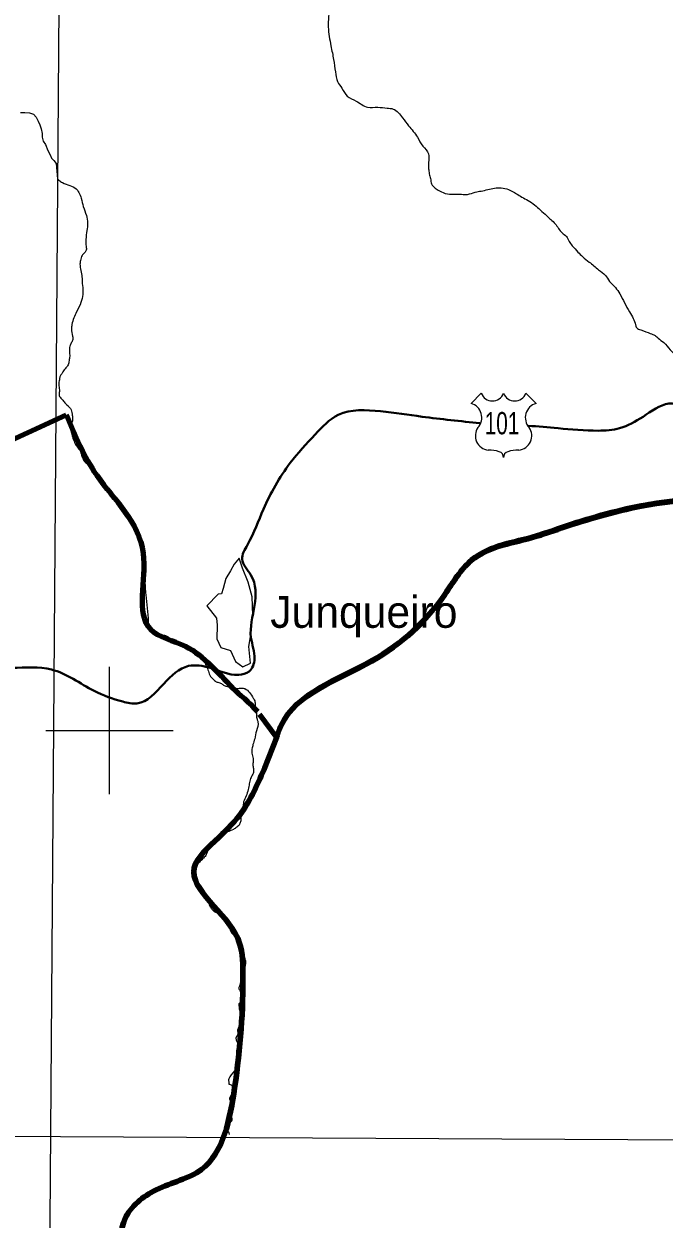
# Model space of a CAD drawing. Extents: x -1643653 to 4543381, y 1624270 to 13878484.
# Drawn here: x 773658 to 783704, y 8892328 to 8911096 of the extents above; entities that cross this region are included whole.
import ezdxf
from ezdxf.enums import TextEntityAlignment as Align

# ---------------------------------------------------------------- set-up
doc = ezdxf.new("R2010")
doc.units = 0
doc.header["$LTSCALE"] = 200
for name, color, linetype, lineweight in [('1', 7, 'Continuous', 13), ('12', 7, 'Continuous', 25), ('2', 7, 'Continuous', 13), ('21', 7, 'Continuous', 25), ('24', 7, 'Continuous', 25), ('48', 7, 'Continuous', 25), ('60', 7, 'Continuous', 13), ('9', 7, 'Continuous', 90)]:
    doc.layers.add(name, color=color, linetype=linetype, lineweight=lineweight)
doc.layers.add('41', color=7, linetype='Continuous')

msp = doc.modelspace()

# ---------------------------------------------------------------- linework, layer by layer
at = {"layer": '1'}
for points in [[(774987.1, 9020818), (774482.3, 8948876), (774053.6, 8890875.3)], [(564751.7, 8894587.5), (664411.9, 8894209.9), (791388.5, 8893536.2)]]:
    msp.add_lwpolyline(points, dxfattribs=at)
at = {"layer": '12', "lineweight": 40}
for points in [[(781569.2, 8904786.7), (782039.7, 8904747.1), (782669.3, 8904708.5), (783006.7, 8904747.1), (783373.7, 8904928.3), (783777.7, 8905132.8), (784291.7, 8905049.2), (784468.4, 8905065.3), (784754.3, 8905737.1), (785107.7, 8905939.5), (785694.7, 8905935.1), (786283.6, 8906023.1), (786505.7, 8906018.9), (787086.7, 8905742.8), (787462.6, 8905479.4)], [(762623.9, 8893658.6), (765112.7, 8894889), (765616.1, 8895112.7), (766035.6, 8895168.6), (766622.8, 8895168.6), (767098.2, 8895308.5), (767433.8, 8895644), (767797.3, 8896343.2), (767965.1, 8896650.8), (768216.8, 8896818.6), (768636.3, 8897489.7), (769335.4, 8898552.4), (769698.9, 8899027.8), (770118.4, 8899810.8), (770454, 8900314.2), (770957.3, 8900677.7), (771712.4, 8900845.5), (772663.2, 8901013.3), (773474.2, 8900985.3), (774089.4, 8900957.3), (774760.5, 8900621.8), (775208, 8900454), (775431.7, 8900426), (775851.2, 8900733.6), (776242.7, 8901013.3), (776578.2, 8900985.3), (777025.7, 8900873.4), (777193.5, 8900929.4), (777277.3, 8901125.1), (777221.4, 8901460.7), (777277.3, 8901964.1), (777221.4, 8902439.5), (777081.6, 8902691.1), (777165.5, 8902914.9), (777417.2, 8903474.2), (777836.6, 8904201.2), (778228.2, 8904648.7), (778591.7, 8904956.3), (779254.3, 8905013.8), (779906, 8904928.3), (780814.8, 8904826.8)]]:
    msp.add_spline(points, degree=3, dxfattribs=at)
at = {"layer": '2'}
for p, q in [((775000, 8899000), (775000, 8901000)), ((774000, 8900000), (776000, 8900000))]:
    msp.add_line(p, q, dxfattribs=at)
at = {"layer": '21'}
msp.add_lwpolyline([(777212.9, 8901059.9), (777186.4, 8901318), (777216.7, 8901500.2), (777250.9, 8901811.5), (777239.5, 8902100), (777175, 8902327.7), (777087.7, 8902547.9), (777034.5, 8902707.3), (776958.6, 8902612.4), (776897.9, 8902509.9), (776825.7, 8902388.4), (776784, 8902232.8), (776761.2, 8902145.5), (776708.1, 8902141.7), (776525.9, 8901955.7), (776681.5, 8901765.9), (776692.9, 8901652), (776685.3, 8901439.5), (776746, 8901302.8), (776897.9, 8901257.2), (776977.6, 8901082.6), (777095.2, 8900999.1)], close=True, dxfattribs=at)
at = {"layer": '24'}
msp.add_lwpolyline([(773604.5, 8909706.9), (773670.6, 8909706.5), (773746.8, 8909700.9), (773807.7, 8909680.2), (773848.1, 8909634), (773883.2, 8909567.6), (773908.3, 8909511.4), (773928.2, 8909450.2), (773942.9, 8909373.7), (773942.6, 8909317.6), (773957.4, 8909256.4), (773997.7, 8909200.1), (774032.7, 8909108.2), (774072.8, 8909031.5), (774092.9, 8908985.6), (774128.2, 8908949.7), (774163.5, 8908903.6), (774185.6, 8908665.7)], dxfattribs=at)
for points in [[(777617.6, 8912828.3), (777839.2, 8912869.9), (777991.6, 8912793.7), (778178.6, 8912766), (778455.7, 8912835.2), (778621.9, 8912856), (778760.5, 8912849.1), (778843.6, 8912745.2), (778864.3, 8912662.1), (778912.8, 8912502.8), (778850.5, 8912322.7), (778739.7, 8912191.1), (778663.5, 8912045.6), (778573.4, 8911865.5), (778497.2, 8911657.7), (778455.7, 8911366.8), (778434.9, 8911048.2), (778476.5, 8910750.4), (778518, 8910535.6), (778545.7, 8910341.7), (778580.4, 8910189.3), (778649.6, 8910085.4), (778732.8, 8909960.8), (778871.3, 8909884.6), (779051.4, 8909787.6), (779210.7, 8909787.6), (779356.1, 8909773.7), (779453.1, 8909759.9), (779598.6, 8909621.3), (779695.5, 8909496.7), (779834.1, 8909316.6), (779917.2, 8909178.1), (780007.2, 8909053.4), (780007.2, 8908921.8), (780009.3, 8908822.2), (780018.8, 8908742.2), (780037.6, 8908666.9), (780056.4, 8908582.2), (780110.5, 8908518.7), (780178.7, 8908476.4), (780303.4, 8908427), (780439.8, 8908424.6), (780552.7, 8908419.9), (780618.6, 8908419.9), (780740.9, 8908452.8), (780832.7, 8908471.7), (780938.5, 8908495.2), (781042, 8908518.7), (781150.2, 8908521.1), (781263.2, 8908495.2), (781387.8, 8908429.3), (781472.5, 8908377.6), (781569, 8908323.5), (781672.5, 8908252.9), (781759.5, 8908175.3)], [(774185.6, 8908665.7), (774206.6, 8908640.3), (774262.2, 8908604.4), (774377, 8908558), (774477.9, 8908507), (774520.8, 8908450.2), (774556.7, 8908357.5), (774590.3, 8908228.8), (774637.8, 8908089.7), (774657, 8907966.8), (774646.5, 8907852.1), (774629.1, 8907712.9), (774632.6, 8907601.7), (774636.1, 8907542.5), (774608.3, 8907500.8), (774570, 8907459.1), (774545.7, 8907382.6), (774537.9, 8907322.4), (774546.2, 8907252.2), (774566.8, 8907147.9), (774572, 8907048.8), (774582.3, 8906929.1), (774580.2, 8906846.2), (774553.4, 8906721.3), (774483.2, 8906572.6), (774441.9, 8906478.6), (774411, 8906374.3), (774403.7, 8906304.8), (774420.2, 8906190.2), (774426.4, 8906138.5), (774400.6, 8906085.9), (774376.9, 8906034.2), (774372.8, 8905948.5), (774375.9, 8905877.3), (774365.5, 8905808.1), (774350, 8905739.9), (774314.9, 8905694.5), (774270.6, 8905633.5), (774243.7, 8905593.3), (774221, 8905553), (774216.9, 8905506.5), (774205.5, 8905472.4), (774207.6, 8905414.6), (774213.8, 8905325.8), (774211.7, 8905257.6), (774247.8, 8905209.1), (774287.1, 8905162.6), (774350, 8905098.6), (774387.2, 8905056.3), (774415, 8904970.4), (774420.2, 8904906.4), (774418.1, 8904863), (774400.6, 8904807.3), (774394.4, 8904756.7), (774392.3, 8904706.1)], [(781759.5, 8908175.3), (781863, 8908083.5), (781926.5, 8908022.4), (781997.1, 8907957.2), (782102.9, 8907815.9), (782171.2, 8907759.5), (782213.5, 8907679.4), (782262.9, 8907613.6), (782352.3, 8907512.3), (782425.2, 8907441.7), (782531.1, 8907357), (782676.9, 8907234.6), (782782.8, 8907147.6), (782848.6, 8907053.4), (782940.4, 8906956.9), (783011, 8906855.7), (783159.2, 8906575.7), (783220.3, 8906469.7), (783255.6, 8906373.2), (783272.1, 8906326.2), (783340.3, 8906290.9), (783488.5, 8906234.4), (783563.8, 8906201.4), (783613.2, 8906161.4), (783697.8, 8906090.8), (783801.3, 8905980.2), (783897.8, 8905874.3), (783959, 8905801.3), (784020.1, 8905744.9), (784166, 8905566), (784241.2, 8905481.3), (784307.1, 8905415.4), (784351.8, 8905340.1), (784389.4, 8905257.7), (784427.1, 8905180), (784502.3, 8905071.8), (784582.3, 8904954.1), (784624.7, 8904890.5), (784660, 8904796.4), (784690.5, 8904709.3), (784692.9, 8904612.8), (784714.1, 8904551.6), (784761.1, 8904448.1), (784855.2, 8904304.5), (784921.1, 8904184.5), (785034, 8904031.5), (785179.8, 8903887.9), (785290.4, 8903796.1), (785433.9, 8903713.8), (785622.1, 8903633.7), (785819.7, 8903567.8), (785993.8, 8903509), (786073.7, 8903483.1), (786156.1, 8903424.3), (786240.8, 8903313.7)], [(774392.3, 8904706.1), (774408.8, 8904660.6), (774419.2, 8904612.1), (774449.1, 8904536.7), (774468.7, 8904491.3), (774507.9, 8904436.5), (774539.9, 8904392.1), (774556.5, 8904343.6), (774580.2, 8904274.3), (774623.5, 8904211.3), (774744.3, 8904094.6), (774766, 8904064.6), (774795.9, 8904014), (774839.2, 8903964.5), (774905.3, 8903868.4), (774960, 8903815.8), (775000.3, 8903755.9), (775044.6, 8903704.2), (775089, 8903634), (775153, 8903546.6), (775202.6, 8903472.3), (775237.7, 8903411.4), (775282, 8903354.6), (775350.7, 8903226.5), (775418.8, 8903065.4), (775490, 8902901.2), (775526.5, 8902794.9), (775551.6, 8902675.7), (775557.9, 8902600.4), (775569.2, 8902517.7), (775565.4, 8902451.2), (775555.4, 8902374.6), (775557.9, 8902305.6), (775559.1, 8902246.7), (775571.7, 8902131.1), (775590.5, 8901919), (775608, 8901708.2), (775616.8, 8901634.1), (775655.7, 8901576.4), (775685.8, 8901541.2), (775722.2, 8901524.9), (775773.6, 8901522.4), (775835.1, 8901502.3), (775892.8, 8901487.2), (775930.4, 8901462.2), (775995.7, 8901423.2), (776059.7, 8901389.4), (776242.1, 8901296.3), (776356.3, 8901236.1), (776415.2, 8901188.4), (776484.2, 8901094.3), (776518.1, 8901016.4), (776553.2, 8900932.3), (776584.6, 8900849.5), (776628.5, 8900806.8)], [(776628.5, 8900806.8), (776674.9, 8900766.7), (776732.6, 8900749.1), (776779, 8900721.5), (776828, 8900697.7), (776930.8, 8900676.3), (776998.6, 8900661.2), (777071.3, 8900666.3), (777125.3, 8900657.5), (777199.6, 8900594.6), (777257.3, 8900509.2), (777283.7, 8900452.8), (777287.4, 8900381.2), (777303.7, 8900309.7), (777306.2, 8900235.6), (777316.3, 8900180.4), (777331.3, 8900136.5), (777307.5, 8899993.4), (777279.9, 8899869.1), (777252.3, 8899778.8), (777237.2, 8899709.7), (777233.4, 8899642.9), (777253.5, 8899560.1), (777253.5, 8899499.9), (777253.5, 8899437.1), (777262.3, 8899365.6), (777249.8, 8899315.4), (777214.6, 8899245.1), (777194.6, 8899163.5), (777177, 8899075.6), (777144.4, 8898972.7), (777105.5, 8898878.2), (777094.2, 8898801.6), (777077.8, 8898718.8), (777062.8, 8898654.8), (777060.3, 8898580.7), (777042.7, 8898530.5), (776998.8, 8898480.3), (776944.9, 8898447.7), (776847, 8898412.5), (776791.8, 8898415.1), (776769.2, 8898415.1), (776723.4, 8898359.3), (776713.4, 8898317.9), (776678.3, 8898272.7), (776641.9, 8898253.9), (776613, 8898251.4), (776586.7, 8898237.6), (776566.6, 8898203.7), (776551.6, 8898159.8), (776534, 8898089.5), (776500.1, 8898022.9), (776449.9, 8897971.5), (776401, 8897921.3), (776365.9, 8897887.4)], [(776365.9, 8897887.4), (776337, 8897852.2), (776322, 8897817.1), (776310.7, 8897755.6), (776314.5, 8897724.2), (776345.8, 8897655.4), (776379.7, 8897601.5), (776422.3, 8897570.1), (776466.2, 8897507.3), (776502.6, 8897448.3), (776539, 8897370.5), (776552.8, 8897306.5), (776564.1, 8897265.1), (776587.9, 8897223.7), (776611.8, 8897188.5), (776684.5, 8897143.3), (776759.8, 8897134.6), (776784.9, 8897119.5), (776803.7, 8897075.6), (776837.6, 8897037.9), (776875.2, 8896999), (776882.7, 8896955.1), (776887.8, 8896884.8), (776899.1, 8896853.4), (776925, 8896814.1), (776977.7, 8896777.7), (777001.5, 8896757.6), (777016.6, 8896726.3), (777024.1, 8896688.6), (777030.3, 8896627.1), (777039.1, 8896585.7), (777056.7, 8896540.5), (777073, 8896504.1), (777101.9, 8896467.7), (777118.2, 8896433.8), (777133.2, 8896384.9), (777134.5, 8896338.4), (777128.2, 8896303.3), (777113.2, 8896253.1), (777096.8, 8896212.9), (777085.6, 8896182.8), (777065.4, 8896101.2), (777056.7, 8896071.1), (777056.7, 8896043.5), (777050.4, 8896017.1), (777040.3, 8895985.7), (777029.1, 8895963.1), (777031.6, 8895941.8), (777045.4, 8895923), (777057.9, 8895882.8), (777067.9, 8895833.9), (777067.9, 8895778.6), (777059.2, 8895742.2), (777040.3, 8895717.1), (777029.1, 8895705.8)], [(777029.1, 8895705.8), (777034.1, 8895656.9), (777037.8, 8895625.5), (777057.9, 8895576.6), (777080.5, 8895531.4), (777089.3, 8895497.5), (777085.5, 8895461.1), (777069.2, 8895412.1), (777051.6, 8895380.8), (777030.3, 8895349.4), (777017.8, 8895319.3), (777011.5, 8895297.9), (777015.2, 8895243.3), (777007.7, 8895217), (776988.9, 8895186.8), (776985.1, 8895163), (776990.1, 8895139.1), (777009, 8895096.5), (777021.5, 8895051.3), (777025.3, 8895023.7), (777002.7, 8894991), (776993.9, 8894953.4), (777001.4, 8894903.2), (776998.9, 8894847.9), (777001.4, 8894802.8), (777011.5, 8894772.7), (776873.4, 8894529.4), (776869.7, 8894500.5), (776873.4, 8894477.9), (776873.4, 8894449.1), (776896, 8894441.5), (776946.2, 8894401.4), (776968.8, 8894385.1), (776941.2, 8894328.6), (776893.5, 8894247), (776883.5, 8894226.9), (776894.7, 8894198), (776918.6, 8894176.7), (776948.7, 8894154.1), (776944.9, 8894129), (776931.1, 8894110.2), (776907.3, 8894075), (776887.2, 8894046.2), (776884.7, 8894021.1), (776893.5, 8893983.4), (776909.8, 8893950.8), (776916.1, 8893923.2), (776921.1, 8893893), (776912.3, 8893867.9), (776865.9, 8893832.8), (776847.1, 8893812.7), (776838.3, 8893767.5), (776840.8, 8893739.9), (776868.4, 8893699.8), (776877.2, 8893658.3)]]:
    msp.add_spline(points, degree=3, dxfattribs=at)
at = {"layer": '48'}
for p, q in [((780675.3, 8905135.7), (780835.3, 8905295.6)), ((781534.6, 8905295.6), (781694.5, 8905135.7))]:
    msp.add_line(p, q, dxfattribs=at)
for centre, radius, start, end in [((781010.1, 8905362.6), 187.2, 200.95927, 339.04073), ((781359.7, 8905362.6), 187.2, 200.95927, 339.04073), ((780613.3, 8904913.8), 230.3, 317.5721, 74.36886), ((781756.6, 8904913.8), 230.3, 105.62774, 222.4279), ((780966.8, 8904628.7), 224.7, 144.73733, 264.65778), ((781403.1, 8904628.7), 224.7, 275.34222, 35.26267), ((780944.8, 8903815.2), 589.7, 72.89371, 89.90057), ((781090.6, 8904288.6), 94.4, 357.69345, 72.92955), ((781279.3, 8904288.6), 94.4, 107.07045, 182.30655), ((781425, 8903815.2), 589.7, 90.09943, 107.10629)]:
    msp.add_arc(centre, radius, start, end, dxfattribs=at)
at = {"layer": '60', "lineweight": 25}
msp.add_spline([(814781, 9009175.5), (814787.2, 9009173.4), (814796.9, 9009173.4), (814799.4, 9009172.4), (814805.1, 9009174.5), (814805.6, 9009176.5), (814811.7, 9009179.5), (814811.7, 9009179.5), (814801.5, 9009181), (814790.7, 9009181.5), (814784.1, 9009183.1), (814777.4, 9009185.1), (814778.4, 9009175.5)], degree=3, dxfattribs=at)
at = {"layer": '9'}
for p, q in [((770082.7, 8903005.7), (774319.9, 8904959.2)), ((770082.7, 8903005.7), (774319.9, 8904959.2)), ((777354.4, 8900257.2), (777624.3, 8899897)), ((777354.4, 8900257.2), (777624.3, 8899897)), ((777421.5, 8899378.1), (777624.7, 8899897.9)), ((777421.5, 8899378.1), (777624.7, 8899897.9)), ((777421.5, 8899378.1), (777624.7, 8899897.9)), ((777433.4, 8899408.6), (777636.6, 8899928.4)), ((777433.4, 8899408.6), (777636.6, 8899928.4))]:
    msp.add_line(p, q, dxfattribs=at)
for points in [[(774319.9, 8904959.2), (774800.3, 8904008.1), (775529.3, 8902785.1), (775645.2, 8901589.1), (776191.3, 8901322.2), (776927.4, 8900677), (777301.9, 8900321), (777321.5, 8900299.2)], [(774319.9, 8904959.2), (774800.3, 8904008.1), (775529.3, 8902785.1), (775645.2, 8901589.1), (776191.3, 8901322.2), (776927.4, 8900677), (777301.9, 8900321), (777321.5, 8900299.2)], [(777620.1, 8899886), (777691.7, 8900069.3), (779119.3, 8901090.4), (780268.4, 8902140.2), (780678.4, 8902667.1), (781187.2, 8902914.3), (781568, 8903011), (782101.4, 8903181.8), (783345.6, 8903521.3), (787274.1, 8903777.8), (790089.1, 8904149.1), (791909.3, 8903747.2), (792712.2, 8902876.5), (792837.1, 8902672.3), (793449.8, 8902739.1)], [(777620.1, 8899886), (777691.7, 8900069.3), (779119.3, 8901090.4), (780268.4, 8902140.2), (780678.4, 8902667.1), (781187.2, 8902914.3), (781568, 8903011), (782101.4, 8903181.8), (783345.6, 8903521.3), (787274.1, 8903777.8), (790089.1, 8904149.1), (791909.3, 8903747.2), (792712.2, 8902876.5), (792837.1, 8902672.3), (793449.8, 8902739.1)], [(777624.7, 8899897.9), (777696.4, 8900081.2), (779123.9, 8901102.4), (780273.1, 8902152.2), (780683, 8902679.1), (781191.8, 8902926.2), (781572.6, 8903022.9), (782106.1, 8903193.7), (783350.3, 8903533.3), (787278.8, 8903789.8), (790093.8, 8904161), (791914, 8903759.1), (792716.9, 8902888.4), (792841.7, 8902684.3), (793454.5, 8902751.1)], [(777624.7, 8899897.9), (777696.4, 8900081.2), (779123.9, 8901102.4), (780273.1, 8902152.2), (780683, 8902679.1), (781191.8, 8902926.2), (781572.6, 8903022.9), (782106.1, 8903193.7), (783350.3, 8903533.3), (787278.8, 8903789.8), (790093.8, 8904161), (791914, 8903759.1), (792716.9, 8902888.4), (792841.7, 8902684.3), (793454.5, 8902751.1)], [(777421.5, 8899378.1), (777078.1, 8898719.8), (776715, 8898321.5), (776332.1, 8897844.8), (777012.8, 8896738.4), (777094.5, 8896207.1), (776964.6, 8894389.8), (776444.2, 8893106.5), (775732.1, 8892785.8), (775246.9, 8892335.8), (775165.8, 8891754.3), (775186.4, 8891222.2), (775285, 8890917.2), (775409.2, 8890637.1), (775534, 8890433), (775531.3, 8890129.1), (775519.2, 8889836.8)], [(777421.5, 8899378.1), (777078.1, 8898719.8), (776715, 8898321.5), (776332.1, 8897844.8), (777012.8, 8896738.4), (777094.5, 8896207.1), (776964.6, 8894389.8), (776444.2, 8893106.5), (775732.1, 8892785.8), (775246.9, 8892335.8), (775165.8, 8891754.3), (775186.4, 8891222.2), (775285, 8890917.2), (775409.2, 8890637.1), (775534, 8890433), (775531.3, 8890129.1), (775519.2, 8889836.8)], [(775519.2, 8889836.8), (775531.3, 8890129.1), (775534, 8890433), (775409.2, 8890637.1), (775285, 8890917.2), (775186.4, 8891222.2), (775165.8, 8891754.3), (775246.9, 8892335.8), (775732.1, 8892785.8), (776444.2, 8893106.5), (776964.6, 8894389.8), (777094.5, 8896207.1), (777012.8, 8896738.4), (776332.1, 8897844.8), (776715, 8898321.5), (777078.1, 8898719.8), (777421.5, 8899378.1)], [(777421.5, 8899378.1), (777078.1, 8898719.8), (776715, 8898321.5), (776332.1, 8897844.8), (777012.8, 8896738.4), (777094.5, 8896207.1), (776964.6, 8894389.8), (776444.2, 8893106.5), (775732.1, 8892785.8), (775246.9, 8892335.8), (775165.8, 8891754.3), (775186.4, 8891222.2), (775285, 8890917.2), (775409.2, 8890637.1), (775534, 8890433), (775531.3, 8890129.1), (775519.2, 8889836.8)]]:
    msp.add_spline(points, degree=3, dxfattribs=at)

# ---------------------------------------------------------------- texts
at = {"layer": '41'}
msp.add_text('Junqueiro', height=500, dxfattribs=at).set_placement((777524.8, 8901612.8))
at = {"layer": '48', "width": 0.7}
msp.add_text('101', height=350, dxfattribs=at).set_placement((781160.7, 8904651.4), align=Align.CENTER)

doc.saveas('drawing.dxf')
